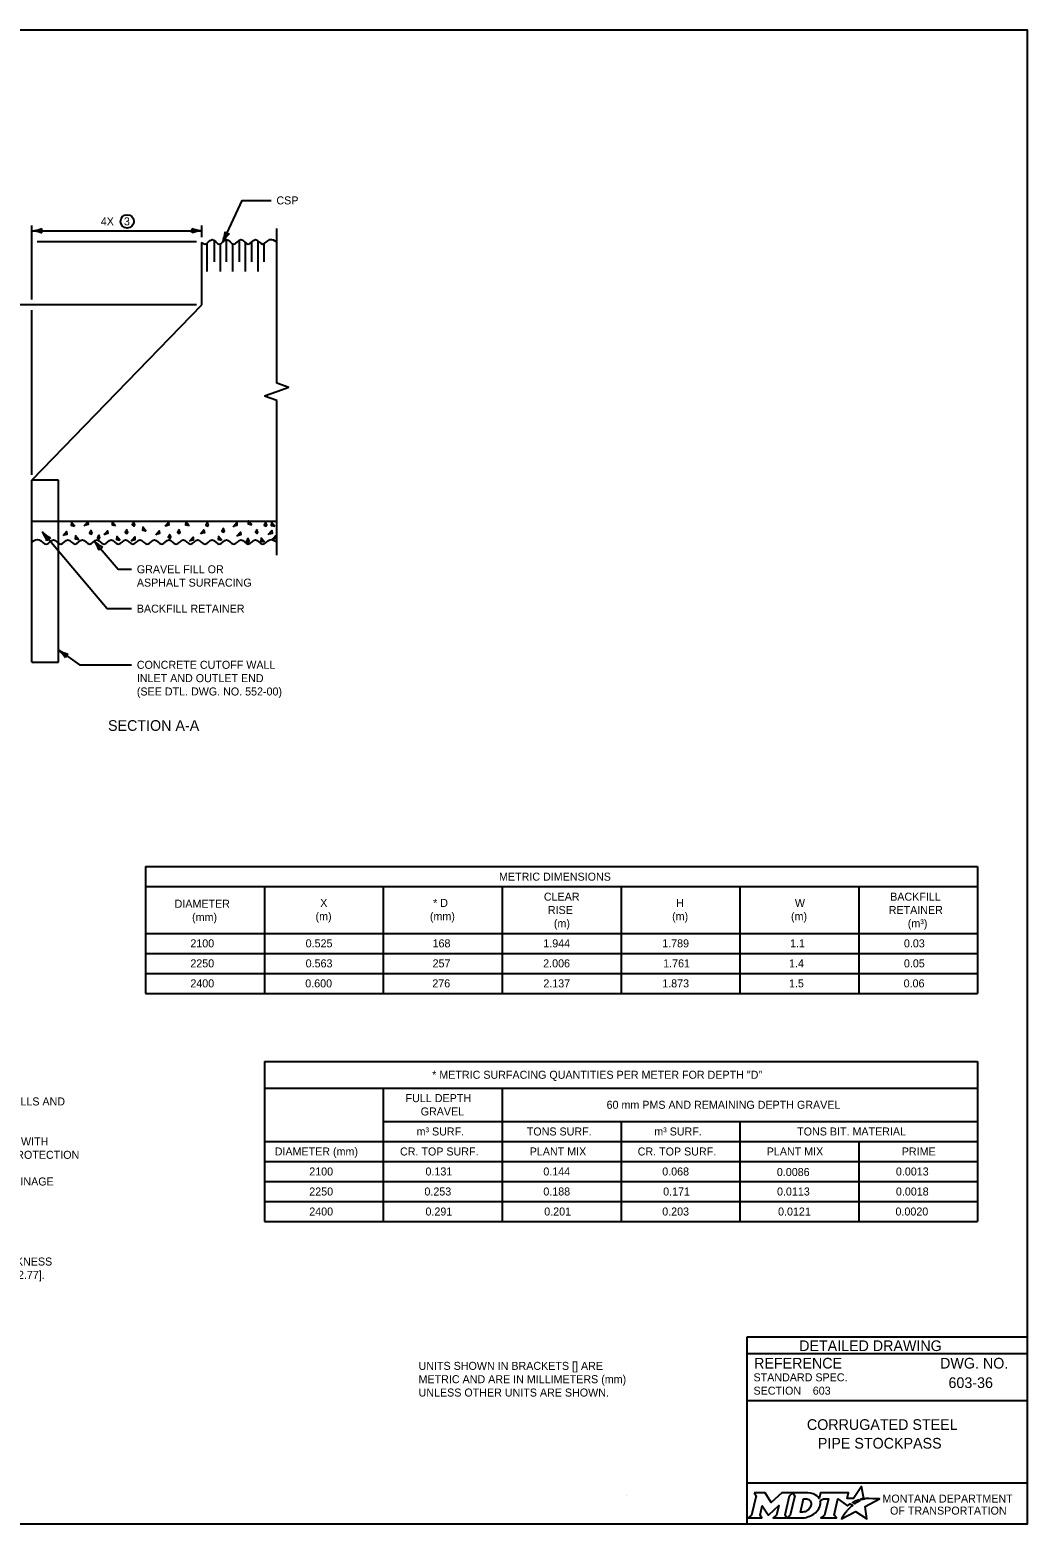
# Model space of a CAD drawing. Extents: x 49991.4 to 50021, y 49987.6 to 50011.4.
# Drawn here: x 50009.28 to 50016.75, y 49987.8 to 49999 of the extents above; entities that cross this region are included whole.
import ezdxf

# ---------------------------------------------------------------- set-up
doc = ezdxf.new("R2010")
doc.units = 0
for name, color, linetype in [('Default', 7, 'Continuous'), ('Level 1', 7, 'Continuous'), ('Level 2', 7, 'Continuous'), ('Level 3', 7, 'Continuous'), ('Level 4', 7, 'Continuous'), ('Level 5', 7, 'Continuous'), ('Level 6', 7, 'Continuous')]:
    doc.layers.add(name, color=color, linetype=linetype)

msp = doc.modelspace()

# ---------------------------------------------------------------- linework, layer by layer
at = {"layer": 'Default'}
for points in [[(50015.513, 49987.981), (50015.502, 49987.987), (50015.514, 49987.99), (50015.526, 49987.991), (50015.508, 49988.082), (50015.449, 49987.99), (50015.401, 49987.99), (50015.412, 49988.034), (50015.202, 49988.034), (50015.192, 49987.991), (50015.186, 49988)], [(50014.706, 49988.034), (50014.72, 49988.01), (50014.686, 49987.867), (50014.66, 49987.845), (50014.762, 49987.845), (50014.749, 49987.867), (50014.765, 49987.937), (50014.809, 49987.868), (50014.814, 49987.868), (50014.889, 49987.938), (50014.872, 49987.867), (50014.848, 49987.845), (50014.949, 49987.845), (50014.936, 49987.868), (50014.969, 49988.011)], [(50014.969, 49988.011), (50014.994, 49988.034), (50014.912, 49988.034), (50014.832, 49987.961), (50014.788, 49988.034), (50014.706, 49988.034)], [(50015.108, 49988.034), (50014.994, 49988.034), (50015.009, 49988.011), (50014.975, 49987.867), (50014.949, 49987.845), (50015.06, 49987.845)], [(50015.132, 49987.947), (50015.13, 49987.939), (50015.127, 49987.93), (50015.123, 49987.922), (50015.118, 49987.914), (50015.111, 49987.907), (50015.103, 49987.901), (50015.095, 49987.896), (50015.086, 49987.892), (50015.077, 49987.89), (50015.067, 49987.889), (50015.052, 49987.889), (50015.075, 49987.989), (50015.091, 49987.989), (50015.099, 49987.988), (50015.106, 49987.986), (50015.113, 49987.983), (50015.119, 49987.979), (50015.124, 49987.974), (50015.128, 49987.968), (50015.13, 49987.962), (50015.132, 49987.955), (50015.132, 49987.952), (50015.132, 49987.947)], [(50015.199, 49987.975), (50015.224, 49987.988), (50015.261, 49987.988), (50015.232, 49987.867), (50015.205, 49987.845), (50015.321, 49987.845), (50015.304, 49987.867), (50015.332, 49987.988), (50015.403, 49987.936), (50015.424, 49987.951), (50015.444, 49987.94)], [(50015.388, 49987.884), (50015.373, 49987.86), (50015.368, 49987.852), (50015.362, 49987.844), (50015.36, 49987.839), (50015.465, 49987.893), (50015.549, 49987.838), (50015.536, 49987.93), (50015.643, 49987.989), (50015.594, 49987.989), (50015.564, 49987.99), (50015.543, 49987.99), (50015.536, 49987.989), (50015.531, 49987.987), (50015.523, 49987.985), (50015.513, 49987.981)], [(50015.462, 49987.954), (50015.46, 49987.952), (50015.442, 49987.961), (50015.452, 49987.967), (50015.456, 49987.969), (50015.465, 49987.973), (50015.47, 49987.976), (50015.478, 49987.979), (50015.485, 49987.982), (50015.497, 49987.974), (50015.493, 49987.972), (50015.489, 49987.97), (50015.484, 49987.967), (50015.479, 49987.965), (50015.478, 49987.963), (50015.475, 49987.962), (50015.472, 49987.96), (50015.47, 49987.959), (50015.467, 49987.957), (50015.465, 49987.955), (50015.462, 49987.954)], [(50015.106, 49987.852), (50015.114, 49987.855), (50015.127, 49987.86), (50015.148, 49987.871)], [(50015.402, 49987.9), (50015.402, 49987.9)]]:
    msp.add_lwpolyline(points, dxfattribs=at)
for centre, radius, start, end in [((50015.131, 49987.955), 0.0709, 339.5329, 15.8582), ((50015.087, 49987.973), 0.118, 300.9103, 339.1383)]:
    msp.add_arc(centre, radius, start, end, dxfattribs=at)
for centre, major_axis, ratio, start_param, end_param in [((50015.106, 49987.986), (0.0834, -0.0037), 0.568097, 0.61298, 1.570796), ((50015.161, 49987.994), (0.0361, -0.0295), 0.469099, 1.225588, 1.570796), ((50015.06, 49987.993), (0, 0.148), 0.987302, 3.139398, 3.456847), ((50015.395, 49987.892), (-0.00694, -0.00806), 0.008222, 0, 3.137361), ((50015.412, 49987.911), (-0.0098, -0.0102), 0.016458, 3.141593, 6.279097), ((50015.433, 49987.93), (-0.0112, -0.0097), 0.021651, 3.157348, 6.283185)]:
    msp.add_ellipse(centre, major_axis=major_axis, ratio=ratio, start_param=start_param, end_param=end_param, dxfattribs=at)
at = {"layer": 'Level 1'}
for p, q in [((50010.567, 49996.938), (50010.567, 49997.405)), ((50010.606, 49997.188), (50010.606, 49997.399)), ((50010.66, 49997.26), (50010.66, 49997.419)), ((50010.706, 49997.188), (50010.706, 49997.396)), ((50010.752, 49997.26), (50010.752, 49997.427)), ((50010.799, 49997.188), (50010.799, 49997.395)), ((50010.847, 49997.26), (50010.847, 49997.423)), ((50010.892, 49997.188), (50010.892, 49997.406)), ((50010.94, 49997.26), (50010.94, 49997.41)), ((50010.987, 49997.188), (50010.987, 49997.416)), ((50011.033, 49997.26), (50011.033, 49997.399)), ((50009.291, 49995.624), (50010.567, 49996.938)), ((50009.291, 49995.317), (50009.291, 49995.624)), ((50009.291, 49994.261), (50009.291, 49995.317)), ((50009.291, 49995.317), (50011.127, 49995.317)), ((50009.491, 49994.261), (50009.491, 49995.317)), ((50009.291, 49994.261), (50009.491, 49994.261))]:
    msp.add_line(p, q, dxfattribs=at)
msp.add_lwpolyline([(49999.384, 49998.999), (50016.75, 49998.999), (50016.75, 49987.799), (49999.384, 49987.799)], close=True, dxfattribs=at)
for points in [[(50009.527, 49995.208), (50009.553, 49995.239), (50009.555, 49995.217), (50009.529, 49995.211)], [(50009.615, 49995.277), (50009.59, 49995.307), (50009.587, 49995.286), (50009.613, 49995.279)], [(50009.685, 49995.282), (50009.711, 49995.312), (50009.713, 49995.291), (50009.687, 49995.284)], [(50009.74, 49995.249), (50009.725, 49995.227), (50009.738, 49995.219), (50009.745, 49995.23), (50009.734, 49995.249)], [(50009.833, 49995.215), (50009.859, 49995.245), (50009.861, 49995.224), (50009.835, 49995.217)], [(50009.921, 49995.282), (50009.895, 49995.312), (50009.893, 49995.29), (50009.919, 49995.284)], [(50010.007, 49995.254), (50009.992, 49995.232), (50010.005, 49995.223), (50010.012, 49995.234), (50010.001, 49995.254)], [(50010.06, 49995.311), (50010.044, 49995.289), (50010.057, 49995.28), (50010.064, 49995.291), (50010.053, 49995.311)], [(50010.149, 49995.24), (50010.123, 49995.271), (50010.121, 49995.249), (50010.146, 49995.243)], [(50010.221, 49995.215), (50010.246, 49995.245), (50010.249, 49995.224), (50010.223, 49995.217)], [(50010.29, 49995.278), (50010.316, 49995.308), (50010.318, 49995.287), (50010.292, 49995.28)], [(50010.399, 49995.254), (50010.384, 49995.232), (50010.397, 49995.223), (50010.404, 49995.234), (50010.393, 49995.254)], [(50010.472, 49995.282), (50010.447, 49995.312), (50010.444, 49995.29), (50010.47, 49995.284)], [(50010.557, 49995.222), (50010.582, 49995.252), (50010.585, 49995.23), (50010.559, 49995.224)], [(50010.612, 49995.308), (50010.597, 49995.287), (50010.61, 49995.278), (50010.617, 49995.289), (50010.606, 49995.308)], [(50010.731, 49995.263), (50010.716, 49995.241), (50010.729, 49995.233), (50010.736, 49995.244), (50010.725, 49995.263)], [(50010.801, 49995.275), (50010.827, 49995.306), (50010.829, 49995.284), (50010.804, 49995.278)], [(50010.829, 49995.205), (50010.855, 49995.235), (50010.857, 49995.213), (50010.831, 49995.207)], [(50010.942, 49995.288), (50010.916, 49995.318), (50010.914, 49995.297), (50010.94, 49995.29)], [(50010.982, 49995.254), (50010.967, 49995.233), (50010.979, 49995.224), (50010.986, 49995.235), (50010.975, 49995.254)], [(50011.049, 49995.308), (50011.033, 49995.286), (50011.046, 49995.278), (50011.053, 49995.289), (50011.042, 49995.308)], [(50011.064, 49995.217), (50011.09, 49995.247), (50011.092, 49995.225), (50011.067, 49995.219)], [(50011.114, 49995.276), (50011.088, 49995.306), (50011.086, 49995.285), (50011.112, 49995.278)], [(50009.645, 49995.176), (50009.619, 49995.206), (50009.617, 49995.184), (50009.643, 49995.178)], [(50009.798, 49995.214), (50009.783, 49995.192), (50009.796, 49995.184), (50009.802, 49995.195), (50009.791, 49995.214)], [(50009.954, 49995.171), (50009.928, 49995.201), (50009.926, 49995.179), (50009.952, 49995.173)], [(50010.037, 49995.167), (50010.063, 49995.198), (50010.065, 49995.176), (50010.04, 49995.17)], [(50010.329, 49995.217), (50010.314, 49995.196), (50010.326, 49995.187), (50010.333, 49995.198), (50010.322, 49995.217)], [(50010.474, 49995.167), (50010.5, 49995.197), (50010.502, 49995.175), (50010.476, 49995.169)], [(50010.716, 49995.172), (50010.691, 49995.202), (50010.688, 49995.181), (50010.714, 49995.174)], [(50010.916, 49995.188), (50010.901, 49995.167), (50010.913, 49995.158), (50010.92, 49995.169), (50010.909, 49995.188)], [(50011.036, 49995.159), (50011.01, 49995.189), (50011.008, 49995.168), (50011.034, 49995.161)], [(50011.093, 49995.177), (50011.119, 49995.207), (50011.121, 49995.186), (50011.095, 49995.179)]]:
    msp.add_lwpolyline(points, dxfattribs=at)
msp.add_arc((50010.568, 49997.405), 0.00029, 67.4125, 186.3273, dxfattribs=at)
for points in [[(50010.568, 49997.405), (50010.589, 49997.394), (50010.643, 49997.427), (50010.697, 49997.394), (50010.751, 49997.427), (50010.805, 49997.394), (50010.859, 49997.427), (50010.913, 49997.394), (50010.967, 49997.427), (50011.021, 49997.394), (50011.075, 49997.427), (50011.127, 49997.411)], [(50009.291, 49995.161), (50009.347, 49995.177), (50009.401, 49995.144), (50009.455, 49995.177), (50009.509, 49995.144), (50009.563, 49995.177), (50009.617, 49995.144), (50009.671, 49995.177), (50009.725, 49995.144), (50009.779, 49995.177), (50009.833, 49995.144), (50009.887, 49995.177), (50009.941, 49995.144), (50009.995, 49995.177), (50010.049, 49995.144), (50010.103, 49995.177), (50010.157, 49995.144), (50010.211, 49995.177), (50010.265, 49995.144), (50010.319, 49995.177), (50010.373, 49995.144), (50010.427, 49995.177), (50010.481, 49995.144), (50010.535, 49995.177), (50010.589, 49995.144), (50010.643, 49995.177), (50010.697, 49995.144), (50010.751, 49995.177), (50010.805, 49995.144), (50010.859, 49995.177), (50010.913, 49995.144), (50010.967, 49995.177), (50011.021, 49995.144), (50011.075, 49995.177), (50011.127, 49995.161)]]:
    msp.add_spline(points, degree=3, dxfattribs=at)
at = {"layer": 'Level 2'}
for p, q in [((50010.145, 49992.727), (50010.145, 49991.777)), ((50010.145, 49992.727), (50016.379, 49992.727)), ((50016.379, 49992.727), (50016.379, 49991.777)), ((50010.145, 49992.577), (50016.379, 49992.577)), ((50011.036, 49992.577), (50011.036, 49991.777)), ((50011.926, 49992.577), (50011.926, 49991.777)), ((50012.817, 49992.577), (50012.817, 49991.777)), ((50013.707, 49992.577), (50013.707, 49991.777)), ((50014.598, 49992.577), (50014.598, 49991.777)), ((50015.489, 49992.577), (50015.489, 49991.777)), ((50010.145, 49992.227), (50016.379, 49992.227)), ((50010.145, 49992.077), (50016.379, 49992.077)), ((50010.145, 49991.927), (50016.379, 49991.927)), ((50010.145, 49991.777), (50016.379, 49991.777)), ((50011.036, 49991.267), (50011.036, 49990.067)), ((50011.036, 49991.267), (50016.379, 49991.267)), ((50016.379, 49991.267), (50016.379, 49990.067)), ((50011.036, 49991.067), (50016.379, 49991.067)), ((50011.926, 49991.067), (50011.926, 49990.067)), ((50012.817, 49991.067), (50012.817, 49990.067)), ((50011.926, 49990.817), (50016.379, 49990.817)), ((50013.707, 49990.817), (50013.707, 49990.067)), ((50014.598, 49990.817), (50014.598, 49990.067)), ((50011.033, 49990.667), (50016.379, 49990.667)), ((50015.489, 49990.667), (50015.489, 49990.067)), ((50011.036, 49990.517), (50016.379, 49990.517)), ((50011.036, 49990.367), (50016.379, 49990.367)), ((50014.598, 49990.382), (50014.598, 49990.167)), ((50011.036, 49990.217), (50016.379, 49990.217)), ((50011.036, 49990.067), (50016.379, 49990.067)), ((50013.746, 49988.012), (50013.746, 49988.012))]:
    msp.add_line(p, q, dxfattribs=at)
msp.add_circle((50010.007, 49997.564), 0.05, dxfattribs=at)
at = {"layer": 'Level 3'}
for p, q in [((50009.291, 49996.978), (50009.291, 49997.534)), ((50009.291, 49997.494), (50010.567, 49997.494)), ((50010.567, 49997.445), (50010.567, 49997.534)), ((50010.527, 49997.411), (50009.331, 49997.411)), ((50010.527, 49996.938), (50009.019, 49996.938)), ((50009.291, 49995.664), (50009.291, 49996.898)), ((50009.491, 49994.351), (50009.649, 49994.24)), ((50009.649, 49994.24), (50010.039, 49994.24))]:
    msp.add_line(p, q, dxfattribs=at)
for points in [[(50010.723, 49997.409), (50010.869, 49997.721), (50011.085, 49997.721)], [(50009.369, 49995.238), (50009.857, 49994.661), (50010.039, 49994.661)], [(50009.76, 49995.168), (50009.939, 49994.956), (50010.039, 49994.956)]]:
    msp.add_lwpolyline(points, dxfattribs=at)
for centre, radius, start, end in [((50009.279, 49997.726), 0.233, 272.8273, 292.0772), ((50009.282, 49997.271), 0.222, 67.456, 87.6395), ((50009.419, 49997.494), 0.0548, 162.1388, 197.8612), ((50010.576, 49997.716), 0.222, 247.456, 267.6395), ((50010.439, 49997.494), 0.0548, 342.1388, 17.8612), ((50010.579, 49997.261), 0.233, 92.8273, 112.0772), ((50010.507, 49997.497), 0.233, 337.7572, 357.007), ((50010.92, 49997.306), 0.222, 132.3859, 152.5694), ((50010.777, 49997.525), 0.0548, 227.0687, 262.791), ((50009.194, 49995.101), 0.222, 17.6831, 37.8666), ((50009.539, 49995.397), 0.233, 223.0544, 242.3043), ((50009.452, 49995.14), 0.0548, 112.366, 148.0883), ((50009.585, 49995.031), 0.222, 17.6753, 37.8588), ((50009.931, 49995.327), 0.233, 223.0466, 242.2965), ((50009.843, 49995.07), 0.0548, 112.3581, 148.0805), ((50009.356, 49994.174), 0.222, 32.487, 52.6705), ((50009.615, 49994.548), 0.233, 237.8583, 257.1081), ((50009.596, 49994.277), 0.0548, 127.1698, 162.8921)]:
    msp.add_arc(centre, radius, start, end, dxfattribs=at)
at = {"layer": 'Level 4'}
for p, q in [((50009.491, 49995.624), (50009.291, 49995.624)), ((50009.491, 49995.317), (50009.491, 49995.624))]:
    msp.add_line(p, q, dxfattribs=at)
at = {"layer": 'Level 5'}
for p, q in [((50016.75, 49989.199), (50014.65, 49989.199)), ((50014.65, 49989.199), (50014.65, 49987.799)), ((50016.75, 49989.074), (50014.65, 49989.074)), ((50016.386, 49988.859), (50016.386, 49988.859)), ((50015.144, 49988.799), (50015.144, 49988.799)), ((50016.75, 49988.724), (50014.65, 49988.724)), ((50015.7, 49988.475), (50015.7, 49988.475)), ((50016.75, 49988.106), (50014.65, 49988.106))]:
    msp.add_line(p, q, dxfattribs=at)
at = {"layer": 'Level 6'}
for p, q in [((50011.127, 49996.351), (50011.127, 49997.511)), ((50011.218, 49996.319), (50011.127, 49996.351)), ((50011.127, 49996.286), (50011.036, 49996.254)), ((50011.127, 49996.221), (50011.036, 49996.254)), ((50011.218, 49996.319), (50011.127, 49996.286)), ((50011.127, 49995.061), (50011.127, 49996.221))]:
    msp.add_line(p, q, dxfattribs=at)

# ---------------------------------------------------------------- texts
at = {"layer": 'Default'}
for s, p in [('MONTANA DEPARTMENT', (50015.666, 49987.96)), ('OF TRANSPORTATION', (50015.723, 49987.87))]:
    msp.add_text(s, height=0.06, dxfattribs=at).set_placement(p)
at = {"layer": 'Level 2'}
for s, height, p in [('CSP', 0.06, (50011.125, 49997.691)), ('4X  ', 0.06, (50009.809, 49997.534)), ('3', 0.06, (50009.982, 49997.534)), ('GRAVEL FILL OR', 0.06, (50010.079, 49994.926)), ('ASPHALT SURFACING', 0.06, (50010.079, 49994.826)), ('BACKFILL RETAINER', 0.06, (50010.079, 49994.631)), ('CONCRETE CUTOFF WALL', 0.06, (50010.079, 49994.21)), ('INLET AND OUTLET END', 0.06, (50010.079, 49994.11)), ('(SEE DTL. DWG. NO. 552-00)', 0.06, (50010.079, 49994.01)), ('SECTION A-A', 0.08, (50009.863, 49993.745)), ('METRIC DIMENSIONS', 0.06, (50012.793, 49992.622)), ('DIAMETER', 0.06, (50010.362, 49992.419)), ('X', 0.06, (50011.453, 49992.425)), ('* D', 0.06, (50012.299, 49992.425)), ('CLEAR', 0.06, (50013.129, 49992.472)), ('RISE', 0.06, (50013.159, 49992.372)), ('H', 0.06, (50014.121, 49992.425)), ('W', 0.06, (50015.01, 49992.425)), ('RETAINER', 0.06, (50015.713, 49992.372)), ('BACKFILL', 0.06, (50015.724, 49992.472)), ('(mm)', 0.06, (50010.493, 49992.319)), ('(m)', 0.06, (50011.418, 49992.325)), ('(mm)', 0.06, (50012.275, 49992.325)), ('(m)', 0.06, (50013.204, 49992.272)), ('(m)', 0.06, (50014.09, 49992.325)), ('(m)', 0.06, (50014.981, 49992.325)), ('(m³)', 0.06, (50015.856, 49992.272)), ('2100', 0.06, (50010.48, 49992.122)), ('0.525', 0.06, (50011.344, 49992.122)), ('168', 0.06, (50012.295, 49992.122)), ('1.944', 0.06, (50013.125, 49992.122)), ('1.789', 0.06, (50014.016, 49992.122)), ('1.1', 0.06, (50014.974, 49992.122)), ('0.03', 0.06, (50015.827, 49992.122)), ('2250', 0.06, (50010.48, 49991.972)), ('0.563', 0.06, (50011.344, 49991.972)), ('257', 0.06, (50012.295, 49991.972)), ('2.006', 0.06, (50013.124, 49991.972)), ('1.761', 0.06, (50014.023, 49991.972)), ('1.4', 0.06, (50014.966, 49991.972)), ('0.05', 0.06, (50015.827, 49991.972)), ('2400', 0.06, (50010.48, 49991.822)), ('0.600', 0.06, (50011.341, 49991.822)), ('276', 0.06, (50012.293, 49991.822)), ('2.137', 0.06, (50013.125, 49991.822)), ('1.873', 0.06, (50014.016, 49991.822)), ('1.5', 0.06, (50014.966, 49991.822)), ('0.06', 0.06, (50015.825, 49991.822)), ('* METRIC SURFACING QUANTITIES PER METER FOR DEPTH "D"', 0.06, (50012.292, 49991.137)), ('UNLESS OTHERWISE SPECIFIED, INSTALL STOCKPASSES WITH CUTOFF WALLS AND', 0.06, (50006.215, 49990.937)), ('FULL DEPTH', 0.06, (50012.093, 49990.962)), ('60 mm PMS AND REMAINING DEPTH GRAVEL', 0.06, (50013.599, 49990.912)), ('GRAVEL', 0.06, (50012.206, 49990.862)), ('m³ SURF.', 0.06, (50012.175, 49990.712)), ('TONS SURF.', 0.06, (50013.001, 49990.712)), ('m³ SURF.', 0.06, (50013.956, 49990.712)), ('TONS BIT. MATERIAL', 0.06, (50015.027, 49990.712)), ('WHEN COMBINATION STOCKPASSES AND DRAINS ARE SPECIFIED, INSTALL WITH ', 0.06, (50006.215, 49990.637)), ('CUTOFF WALLS, BACKFILL RETAINERS AT BOTH ENDS, CONCRETE EDGE PROTECTION', 0.06, (50006.215, 49990.537)), ('DIAMETER (mm)', 0.06, (50011.112, 49990.562)), ('CR. TOP SURF.', 0.06, (50012.051, 49990.562)), ('PLANT MIX', 0.06, (50013.023, 49990.562)), ('CR. TOP SURF.', 0.06, (50013.832, 49990.562)), ('PLANT MIX', 0.06, (50014.799, 49990.562)), ('PRIME', 0.06, (50015.811, 49990.562)), ('2100', 0.06, (50011.371, 49990.412)), ('0.131', 0.06, (50012.242, 49990.412)), ('0.144', 0.06, (50013.125, 49990.412)), ('0.068', 0.06, (50014.016, 49990.412)), ('0.0086', 0.06, (50014.875, 49990.408)), ('0.0013', 0.06, (50015.767, 49990.412)), ('ASPHALT SURFACING; CROSS SLOPE ASPHALT SURFACING TO ALLOW DRAINAGE', 0.06, (50006.215, 49990.337)), ('2250', 0.06, (50011.371, 49990.262)), ('0.253', 0.06, (50012.234, 49990.262)), ('0.188', 0.06, (50013.125, 49990.262)), ('0.171', 0.06, (50014.023, 49990.262)), ('0.0113', 0.06, (50014.876, 49990.262)), ('0.0018', 0.06, (50015.767, 49990.262)), ('2400', 0.06, (50011.371, 49990.112)), ('0.291', 0.06, (50012.242, 49990.112)), ('0.201', 0.06, (50013.132, 49990.112)), ('0.203', 0.06, (50014.016, 49990.112)), ('0.0121', 0.06, (50014.884, 49990.112)), ('0.0020', 0.06, (50015.764, 49990.112)), ('CORRUGATED STEEL PIPE STOCKPASS IS 0.079" [2.01].  THE MINIMUM THICKNESS', 0.06, (50006.215, 49989.737)), ('FOR 96" [2400] DIAMETER CORRUGATED STEEL PIPE STOCKPASS IS 0.109" [2.77].', 0.06, (50006.215, 49989.637)), ('UNITS SHOWN IN BRACKETS [] ARE ', 0.06, (50012.19, 49988.955)), ('METRIC AND ARE IN MILLIMETERS (mm) ', 0.06, (50012.19, 49988.855)), ('603-36', 0.08, (50016.161, 49988.819)), ('UNLESS OTHER UNITS ARE SHOWN.', 0.06, (50012.19, 49988.755)), ('603', 0.06, (50015.144, 49988.769)), ('CORRUGATED STEEL', 0.08, (50015.1, 49988.505)), ('PIPE STOCKPASS', 0.08, (50015.182, 49988.365))]:
    msp.add_text(s, height=height, dxfattribs=at).set_placement(p)
at = {"layer": 'Level 5'}
for s, height, p in [('DETAILED DRAWING', 0.0799, (50015.042, 49989.096)), ('REFERENCE', 0.08, (50014.704, 49988.965)), ('DWG. NO.', 0.08, (50016.098, 49988.965)), ('STANDARD SPEC.', 0.06, (50014.7, 49988.869)), ('SECTION', 0.06, (50014.7, 49988.769))]:
    msp.add_text(s, height=height, dxfattribs=at).set_placement(p)

doc.saveas('drawing.dxf')
